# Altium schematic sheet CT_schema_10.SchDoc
size 274 x 160 mm
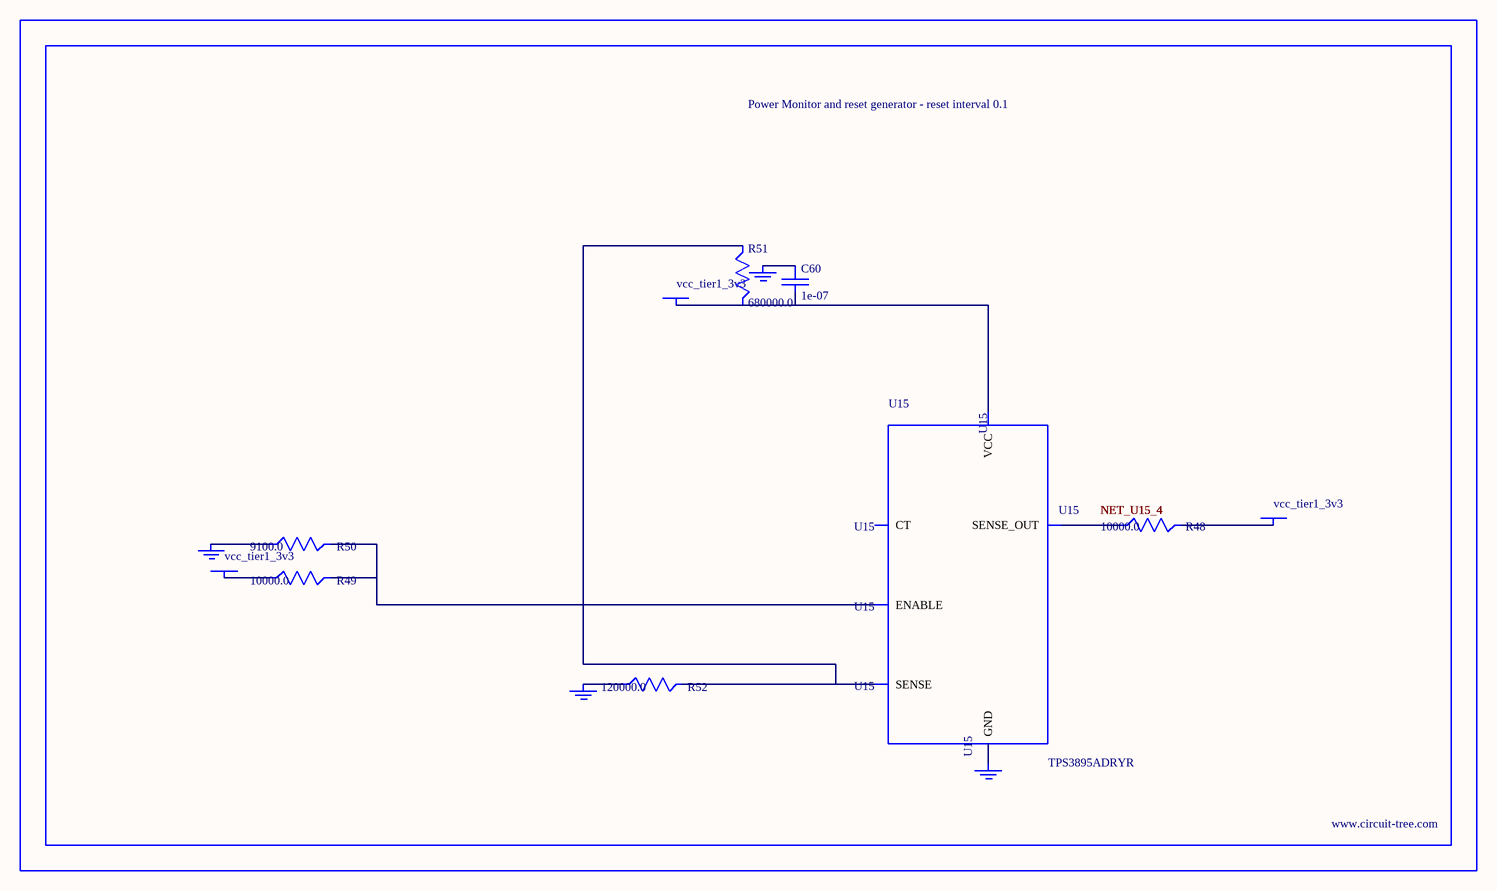
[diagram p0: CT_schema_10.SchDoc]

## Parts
BORDER9  (no value)
C60  1e-07  [C0402]
GND_INSTANCE_9_0  (no value)
GND_INSTANCE_9_1  (no value)
GND_INSTANCE_9_2  (no value)
GND_INSTANCE_9_3  (no value)
POWER_INSTANCE_9_0  vcc_tier1_3v3
POWER_INSTANCE_9_1  vcc_tier1_3v3
POWER_INSTANCE_9_2  vcc_tier1_3v3
R48  10000.0  [R0603]
R49  10000.0  [R0603]
R50  9100.0  [R0603]
R51  680000.0  [R0603]
R52  120000.0  [R0603]
U15  TPS3895ADRYR  [SON-6]

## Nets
NetC60_1: C60.1 GND_INSTANCE_9_2.0(GND)
NetC60_2: C60.2 POWER_INSTANCE_9_2.0(PWR) R51.2 U15.6(VCC)
NetGND_INSTANCE_9_0_0: GND_INSTANCE_9_0.0(GND) R50.1
NetGND_INSTANCE_9_1_0: GND_INSTANCE_9_1.0(GND) R52.1
NetGND_INSTANCE_9_3_0: GND_INSTANCE_9_3.0(GND) U15.2(GND)
NetPOWER_INSTANCE_9_0_0: POWER_INSTANCE_9_0.0(PWR) R49.1
NetPOWER_INSTANCE_9_1_0: POWER_INSTANCE_9_1.0(PWR) R48.2
NetR48_1: R48.1 U15.4(SENSE_OUT)
NetR49_2: R49.2 R50.2 U15.1(ENABLE)
NetR51_1: R51.1 R52.2 U15.3(SENSE)

Not connected (* = marked no-connect by the designer): U15 5(CT)

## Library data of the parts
BORDER9 = BORDER_PAGE9
C60 = C0402C104K3RACTU
GND_INSTANCE_9_0-GND_INSTANCE_9_3 = GND
POWER_INSTANCE_9_0-POWER_INSTANCE_9_2 = PWR
R48 R49 = RC0603JR-0710KL
R50 = RC0603JR-079K1L
R51 = RC0603JR-07680KL
R52 = RC0603JR-07120KL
